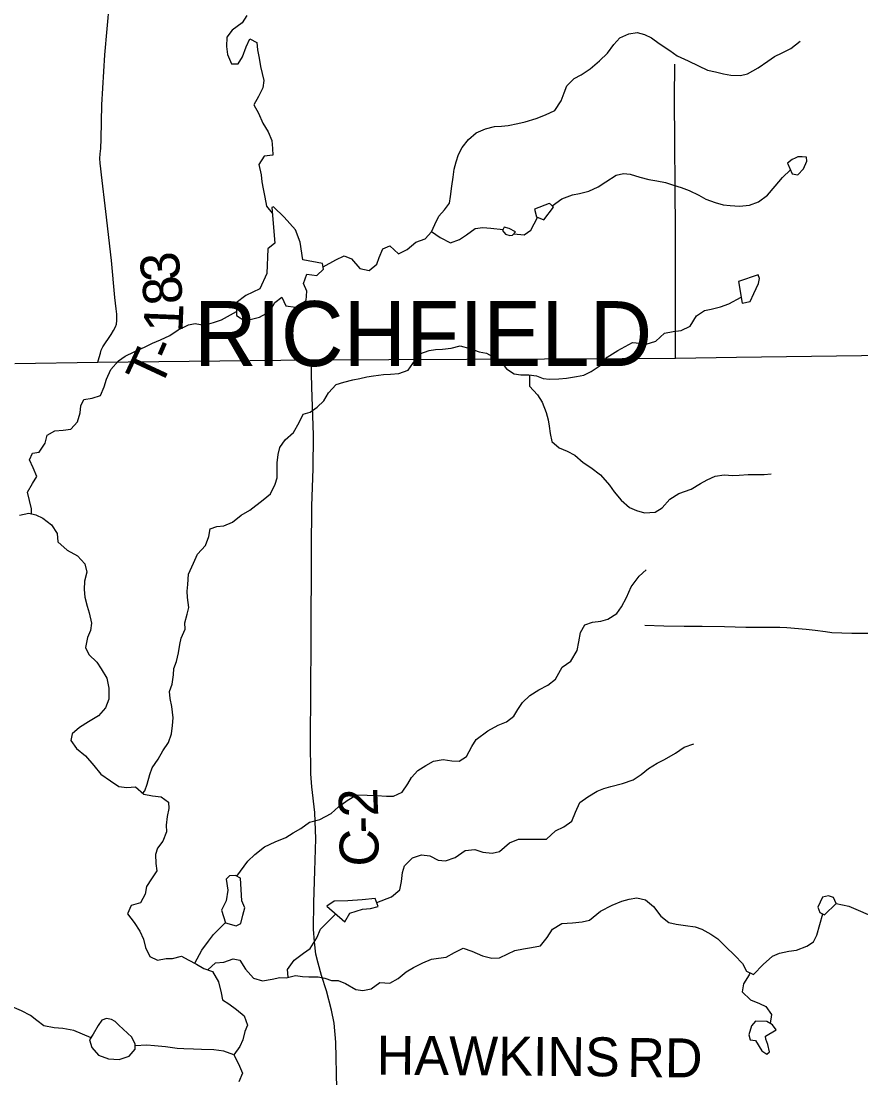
# Model space of a CAD drawing. Extents: x 0 to 34, y 0 to 22.
# Drawn here: x 3.306 to 4.531, y 17.388 to 18.93 of the extents above; entities that cross this region are included whole.
import ezdxf

# ---------------------------------------------------------------- set-up
doc = ezdxf.new("R2010")
doc.units = 0
for name, color, linetype in [('GM_X_City_Street', 7, 'Continuous'), ('GM_X_Corporation_Text', 7, 'Continuous'), ('GM_X_County_Road', 7, 'Continuous'), ('GM_X_County_Road_Text', 7, 'Continuous'), ('GM_X_Minor_Lake', 7, 'Continuous'), ('GM_X_Minor_River', 7, 'Continuous'), ('GM_X_State_Route', 7, 'Continuous'), ('GM_X_Township_Road', 7, 'Continuous'), ('GM_X_Township_Road_Text', 7, 'Continuous')]:
    doc.layers.add(name, color=color, linetype=linetype)

msp = doc.modelspace()

# ---------------------------------------------------------------- linework, layer by layer
at = {"layer": 'GM_X_City_Street'}
for points in [[(4.2606, 18.4383), (4.2606, 18.6235), (4.2594, 18.817), (4.2597, 18.8672)], [(4.2162, 18.0489), (4.2437, 18.0478), (4.2733, 18.0471), (4.2997, 18.0473), (4.3324, 18.0466), (4.3635, 18.0457), (4.4129, 18.0457), (4.4231, 18.0455), (4.4513, 18.0431), (4.4645, 18.0416), (4.4794, 18.0396), (4.4887, 18.0382), (4.5182, 18.0369), (4.5682, 18.0371)]]:
    msp.add_lwpolyline(points, dxfattribs=at)
at = {"layer": 'GM_X_County_Road'}
msp.add_lwpolyline([(3.7668, 17.3723), (3.7653, 17.4403), (3.7626, 17.4681), (3.7588, 17.4874), (3.7514, 17.5153), (3.7444, 17.5379), (3.7392, 17.5557), (3.7362, 17.5687), (3.7341, 17.5867), (3.7327, 17.6053), (3.7331, 17.644), (3.7347, 17.6903), (3.7359, 17.7372), (3.7343, 17.7754), (3.73, 17.8128), (3.7286, 17.8317), (3.7281, 17.8794), (3.729, 18.0253), (3.7295, 18.1581), (3.73, 18.2228), (3.7321, 18.2766), (3.7327, 18.326), (3.7301, 18.3961), (3.729, 18.4357)], dxfattribs=at)
at = {"layer": 'GM_X_Minor_Lake'}
for points in [[(4.4241, 18.7226), (4.4311, 18.7071), (4.439, 18.7057), (4.4473, 18.7145), (4.4521, 18.7255), (4.4517, 18.7316), (4.4453, 18.7319)], [(4.4453, 18.7319), (4.4393, 18.7318), (4.4354, 18.7302), (4.4309, 18.728), (4.4241, 18.7226)], [(3.676, 18.6061), (3.6659, 18.5977), (3.6647, 18.562), (3.6542, 18.5394), (3.6338, 18.5297), (3.6199, 18.519), (3.6204, 18.5007), (3.6323, 18.4925), (3.6538, 18.498), (3.669, 18.5061), (3.676, 18.5195), (3.6866, 18.5272), (3.692, 18.5147), (3.7065, 18.5129), (3.7219, 18.5226), (3.723, 18.5359), (3.7179, 18.5473), (3.7227, 18.5606), (3.7375, 18.5588), (3.7473, 18.5681), (3.7457, 18.5764), (3.7172, 18.5818), (3.7132, 18.6076), (3.7062, 18.6254), (3.6897, 18.6439), (3.6744, 18.6589)], [(3.6744, 18.6589), (3.6717, 18.6581), (3.676, 18.6061)], [(4.0551, 18.6557), (4.0578, 18.6443), (4.0685, 18.6399), (4.0827, 18.6586), (4.0785, 18.6631), (4.0762, 18.6639)], [(4.0762, 18.6639), (4.0551, 18.6557)], [(4.0273, 18.6227), (4.0181, 18.6272), (4.0109, 18.6294), (4.0083, 18.6245), (4.0129, 18.6192)], [(4.0129, 18.6192), (4.0189, 18.6171), (4.0228, 18.6177), (4.0273, 18.6227)], [(4.358, 18.5183), (4.3697, 18.5207), (4.3749, 18.5325), (4.382, 18.5474), (4.3835, 18.5547), (4.3811, 18.56), (4.3524, 18.5502)], [(4.3524, 18.5502), (4.358, 18.5183)], [(3.6263, 17.6797), (3.6187, 17.6838), (3.6099, 17.6829), (3.605, 17.6783), (3.6075, 17.662), (3.6053, 17.6468), (3.5982, 17.633), (3.6041, 17.6148), (3.6197, 17.6101), (3.6265, 17.6135), (3.6294, 17.6257), (3.6324, 17.6364), (3.6281, 17.6466)], [(3.6281, 17.6466), (3.6263, 17.6797)], [(4.4949, 17.643), (4.4914, 17.6513), (4.4838, 17.6539), (4.4754, 17.6519), (4.4684, 17.6374), (4.4711, 17.6298), (4.4783, 17.6261)], [(3.7783, 17.6161), (3.7857, 17.6287), (3.8043, 17.6346), (3.8157, 17.6355), (3.827, 17.6386), (3.8227, 17.65), (3.8034, 17.6479), (3.7829, 17.6466), (3.7628, 17.6464), (3.7519, 17.639)], [(3.7519, 17.639), (3.7783, 17.6161)], [(4.4783, 17.6261), (4.4949, 17.643)], [(3.424, 17.4726), (3.4184, 17.4649), (3.4113, 17.4523), (3.406, 17.4439), (3.4092, 17.4329), (3.4187, 17.4216), (3.4336, 17.416), (3.4492, 17.4154), (3.4639, 17.4201), (3.4726, 17.4305), (3.4725, 17.4377), (3.4675, 17.4479)], [(3.4675, 17.4479), (3.4485, 17.4651), (3.443, 17.4707), (3.4378, 17.4734), (3.4308, 17.4749), (3.424, 17.4726)], [(4.4077, 17.4586), (4.4023, 17.4658), (4.3939, 17.4707), (4.3776, 17.4713), (4.3716, 17.4644), (4.3676, 17.451), (4.3695, 17.4438), (4.3775, 17.4428), (4.3867, 17.4277), (4.394, 17.4228), (4.3981, 17.4263), (4.3954, 17.4372), (4.3927, 17.4448), (4.3922, 17.449)], [(4.3922, 17.449), (4.4077, 17.4586)]]:
    msp.add_lwpolyline(points, dxfattribs=at)
at = {"layer": 'GM_X_Minor_River'}
for points in [[(3.6351, 18.9379), (3.6287, 18.9275), (3.614, 18.9168), (3.6062, 18.9064), (3.6055, 18.8931), (3.6071, 18.881), (3.613, 18.8677), (3.6228, 18.8674), (3.6288, 18.8778), (3.6344, 18.8923), (3.6396, 18.9041), (3.6499, 18.8989), (3.6511, 18.8878), (3.6535, 18.8757), (3.6551, 18.8639), (3.6575, 18.8533), (3.6599, 18.8435), (3.6588, 18.8328), (3.6525, 18.8198), (3.6454, 18.8076), (3.6523, 18.7955), (3.6585, 18.7811), (3.6666, 18.7683), (3.6716, 18.7558), (3.6729, 18.744), (3.6734, 18.7342), (3.6605, 18.7329), (3.6526, 18.721), (3.6562, 18.7055), (3.6574, 18.6956), (3.659, 18.6854), (3.6614, 18.6729), (3.6642, 18.66), (3.6724, 18.6497)], [(3.7467, 18.5715), (3.7654, 18.5815), (3.7775, 18.5877), (3.7878, 18.5833), (3.8004, 18.5689), (3.8138, 18.566), (3.8251, 18.5752), (3.8284, 18.5852), (3.8336, 18.5977), (3.8442, 18.602), (3.8568, 18.5904), (3.8693, 18.5966), (3.8821, 18.6077), (3.8957, 18.6124), (3.9047, 18.6227), (3.9095, 18.6334), (3.9155, 18.6453), (3.9238, 18.6548), (3.9309, 18.6644), (3.9323, 18.6739), (3.9345, 18.6891), (3.9362, 18.7021), (3.9377, 18.7142), (3.9406, 18.7245), (3.9443, 18.7356), (3.9495, 18.7455), (3.9585, 18.757), (3.9698, 18.767), (3.9834, 18.7728), (3.9967, 18.776), (4.0069, 18.7768), (4.0168, 18.7777), (4.0308, 18.7805), (4.0414, 18.7829), (4.0573, 18.7879), (4.0709, 18.793), (4.0849, 18.7996), (4.0939, 18.8137), (4.0983, 18.8252), (4.102, 18.8355), (4.1129, 18.8462), (4.1231, 18.8516), (4.1363, 18.8605), (4.1499, 18.872), (4.1616, 18.8832), (4.1709, 18.8958), (4.1796, 18.9057), (4.1928, 18.9112), (4.2049, 18.9132), (4.2156, 18.9103), (4.2259, 18.9054), (4.2369, 18.8975), (4.2526, 18.8871), (4.2633, 18.8792), (4.2793, 18.8721), (4.2942, 18.8646), (4.3075, 18.8583), (4.3193, 18.8561), (4.3307, 18.8532), (4.3413, 18.851), (4.3554, 18.8508), (4.3656, 18.8532), (4.3815, 18.862), (4.3954, 18.8717), (4.4052, 18.8782), (4.4162, 18.8837), (4.429, 18.8902), (4.4426, 18.9006)], [(4.0809, 18.6606), (4.0948, 18.6709), (4.1103, 18.6767), (4.1205, 18.6787), (4.1345, 18.6819), (4.1481, 18.6881), (4.1591, 18.6954), (4.1742, 18.7054), (4.1851, 18.7078), (4.1946, 18.7068), (4.2087, 18.7023), (4.222, 18.6991), (4.2334, 18.6969), (4.246, 18.6943), (4.2578, 18.6907), (4.2692, 18.687), (4.2806, 18.6829), (4.2947, 18.6762), (4.305, 18.6702), (4.3187, 18.6654), (4.3305, 18.6621), (4.3404, 18.661), (4.3541, 18.66), (4.3685, 18.6613), (4.3817, 18.6664), (4.3949, 18.676), (4.4062, 18.6894), (4.4167, 18.7016), (4.4283, 18.7131)], [(4.0247, 18.6198), (4.0398, 18.6183), (4.0496, 18.6252), (4.0596, 18.6436)], [(3.9048, 18.6229), (3.9173, 18.6141), (3.9326, 18.6063), (3.9458, 18.6113), (3.9556, 18.6183), (3.9684, 18.6275), (3.9798, 18.6291), (3.9912, 18.6281), (4.0091, 18.626)], [(4.282, 18.4849), (4.2914, 18.4998), (4.3031, 18.5079), (4.3129, 18.5099), (4.3262, 18.5131), (4.3386, 18.5174), (4.3564, 18.5274)], [(3.321, 18.2113), (3.3213, 18.2186), (3.3181, 18.2307), (3.3154, 18.2429), (3.3225, 18.2555), (3.3288, 18.2658), (3.3238, 18.2783), (3.3184, 18.29), (3.3224, 18.2999), (3.3323, 18.3012), (3.3413, 18.3142), (3.3442, 18.326), (3.3552, 18.3322), (3.3673, 18.333), (3.3787, 18.3347), (3.3884, 18.3454), (3.3921, 18.3584), (3.3932, 18.3686), (3.3976, 18.3782), (3.4098, 18.3798), (3.4219, 18.3837), (3.4271, 18.3963), (3.4304, 18.4077), (3.4371, 18.4219), (3.448, 18.4345), (3.4578, 18.4411), (3.471, 18.4473), (3.4869, 18.4546), (3.4978, 18.4601), (3.5092, 18.4651), (3.5232, 18.4713), (3.5352, 18.4794), (3.55, 18.4868), (3.5598, 18.4888), (3.5731, 18.4862), (3.5867, 18.4905), (3.5985, 18.4944), (3.6203, 18.5062)], [(3.4835, 17.8037), (3.4866, 17.8071), (3.49, 17.8167), (3.4936, 17.8308), (3.4973, 17.8407), (3.5059, 17.8533), (3.5127, 17.8655), (3.5209, 17.8778), (3.5253, 17.8903), (3.5268, 17.9025), (3.5278, 17.9135), (3.5261, 17.9299), (3.5237, 17.942), (3.5225, 17.9519), (3.5266, 17.9626), (3.5284, 17.9763), (3.5287, 17.9858), (3.5327, 17.9957), (3.5357, 18.0086), (3.5375, 18.0204), (3.5393, 18.0299), (3.5452, 18.0429), (3.5451, 18.0524), (3.5481, 18.0646), (3.5506, 18.0745), (3.5486, 18.0889), (3.5485, 18.0984), (3.5492, 18.1079), (3.5502, 18.1231), (3.5573, 18.1392), (3.5632, 18.1525), (3.5752, 18.1648), (3.5801, 18.1781), (3.5819, 18.1895), (3.5917, 18.1927), (3.6019, 18.1939), (3.6144, 18.199), (3.6272, 18.2094), (3.6397, 18.2163), (3.6593, 18.2317), (3.6698, 18.2405), (3.6769, 18.2543), (3.6795, 18.2638), (3.6798, 18.2748), (3.6797, 18.2855), (3.6811, 18.2976), (3.6836, 18.3079), (3.6911, 18.319), (3.7032, 18.3298), (3.7118, 18.3443), (3.7177, 18.3565), (3.7276, 18.3596), (3.7378, 18.3666), (3.7475, 18.3762), (3.7546, 18.3876), (3.7659, 18.3999), (3.7769, 18.4034), (3.7898, 18.4066), (3.8, 18.4086), (3.8102, 18.411), (3.8201, 18.4126), (3.8345, 18.4146), (3.8451, 18.4151), (3.8572, 18.416), (3.8705, 18.421), (3.8776, 18.4306), (3.8877, 18.4444), (3.9013, 18.4494), (3.9108, 18.4507), (3.9207, 18.4515), (3.9336, 18.4528), (3.9468, 18.4563), (3.9609, 18.4523), (3.9742, 18.4475), (3.9848, 18.4457), (3.9963, 18.4393), (4.0062, 18.4329), (4.0143, 18.4228), (4.0253, 18.4153), (4.0352, 18.4138), (4.0466, 18.4139), (4.058, 18.4125), (4.0675, 18.4088), (4.077, 18.4078), (4.0903, 18.4079), (4.1017, 18.4091), (4.1161, 18.4116), (4.1271, 18.4136), (4.1376, 18.4186), (4.1508, 18.4275), (4.161, 18.4397), (4.1765, 18.4494), (4.1874, 18.4555), (4.198, 18.461), (4.2086, 18.4603), (4.2181, 18.4589), (4.2321, 18.4632), (4.2445, 18.4747), (4.2574, 18.4771), (4.2688, 18.4787), (4.282, 18.4849)], [(4.0479, 18.4138), (4.0479, 18.3976), (4.0594, 18.3848), (4.0663, 18.3742), (4.0721, 18.3591), (4.0749, 18.3485), (4.0765, 18.339), (4.0777, 18.3284), (4.0805, 18.3166), (4.0908, 18.3076), (4.1026, 18.3028), (4.1141, 18.2968), (4.1259, 18.2859), (4.137, 18.2788), (4.1515, 18.2679), (4.1646, 18.2532), (4.1711, 18.2434), (4.1814, 18.2313), (4.1937, 18.2204), (4.204, 18.2159), (4.2154, 18.2126), (4.2313, 18.2135), (4.2415, 18.2201), (4.2524, 18.2327), (4.2656, 18.2408), (4.2838, 18.2471), (4.297, 18.2552), (4.3068, 18.2606), (4.3185, 18.266), (4.3318, 18.268), (4.3443, 18.267), (4.3538, 18.2675), (4.3667, 18.2684), (4.3902, 18.2686), (4.4001, 18.2694)], [(3.3035, 18.2093), (3.3172, 18.2121), (3.3274, 18.2099), (3.3377, 18.2047), (3.3503, 18.1953), (3.3584, 18.1825), (3.3597, 18.1703), (3.373, 18.1583), (3.3883, 18.1497), (3.399, 18.1384), (3.4018, 18.1263), (3.3985, 18.113), (3.3978, 18.1008), (3.3991, 18.0898), (3.4026, 18.0765), (3.4054, 18.0667), (3.4085, 18.0519), (3.4071, 18.0412), (3.403, 18.0309), (3.4001, 18.0161), (3.4048, 18.0059), (3.4166, 17.995), (3.4228, 17.9851), (3.4309, 17.9715), (3.4341, 17.9567), (3.4338, 17.9408), (3.429, 17.9282), (3.4189, 17.9163), (3.4041, 17.9078), (3.3913, 17.8993), (3.3804, 17.8901), (3.3786, 17.8806), (3.3866, 17.8689), (3.4, 17.858), (3.4123, 17.8441), (3.4223, 17.8316), (3.4364, 17.8219), (3.4486, 17.8132), (3.4604, 17.8118), (3.4729, 17.8131), (3.4851, 17.8022), (3.4977, 17.8), (3.5102, 17.7986), (3.5209, 17.7908), (3.5214, 17.7813), (3.5192, 17.7695), (3.5178, 17.7569), (3.5179, 17.7474), (3.5127, 17.7337), (3.5052, 17.7237), (3.5023, 17.7142), (3.5028, 17.7009), (3.504, 17.6903), (3.4961, 17.6788), (3.489, 17.6677), (3.4868, 17.6563), (3.4801, 17.6437), (3.4665, 17.6398), (3.4613, 17.6279), (3.4709, 17.6151), (3.4794, 17.6023), (3.4844, 17.5905), (3.4875, 17.5784), (3.4937, 17.5655), (3.5048, 17.56), (3.5177, 17.5627), (3.5271, 17.5624), (3.54, 17.566), (3.5496, 17.5608), (3.5618, 17.5544), (3.5724, 17.5481), (3.585, 17.5436), (3.5939, 17.5285), (3.5978, 17.5126), (3.5998, 17.5023), (3.6093, 17.4963), (3.6204, 17.4881), (3.6315, 17.4791), (3.6362, 17.4654), (3.6325, 17.4559), (3.6295, 17.4437), (3.6251, 17.4342), (3.6165, 17.4219), (3.623, 17.4087), (3.6288, 17.3951), (3.6236, 17.3825)], [(3.6207, 17.6827), (3.6367, 17.7044), (3.6472, 17.714), (3.6612, 17.7256), (3.6767, 17.7329), (3.6922, 17.7388), (3.7031, 17.7457), (3.714, 17.7523), (3.7269, 17.7612), (3.7416, 17.7655), (3.7582, 17.774), (3.7692, 17.7836), (3.7816, 17.7932), (3.7952, 17.8013), (3.8111, 17.8007), (3.8252, 17.8001), (3.8392, 17.7995), (3.8495, 17.7992), (3.8619, 17.8054), (3.8702, 17.8172), (3.8754, 17.8268), (3.8848, 17.8367), (3.8965, 17.8441), (3.9078, 17.8503), (3.9219, 17.8527), (3.9344, 17.8509), (3.945, 17.8506), (3.9556, 17.8572), (3.9634, 17.8717), (3.9698, 17.882), (3.9868, 17.8947), (4.0022, 17.9028), (4.0143, 17.9079), (4.0249, 17.916), (4.0309, 17.9259), (4.0376, 17.9358), (4.0481, 17.9462), (4.0614, 17.9543), (4.0746, 17.9613), (4.0855, 17.9701), (4.0956, 17.9873), (4.108, 17.9965), (4.1174, 18.0118), (4.1199, 18.0244), (4.1221, 18.0381), (4.1284, 18.0495), (4.1394, 18.0531), (4.1519, 18.0547), (4.1618, 18.0575), (4.175, 18.0659), (4.1821, 18.0755), (4.1892, 18.0889), (4.1962, 18.1045), (4.2079, 18.1202), (4.2177, 18.1294)], [(3.8249, 17.6442), (3.8466, 17.6525), (3.8587, 17.6628), (3.8612, 17.675), (3.8626, 17.688), (3.8652, 17.6975), (3.8768, 17.7094), (3.8901, 17.7137), (3.9022, 17.7123), (3.9144, 17.7059), (3.9251, 17.7049), (3.9395, 17.71), (3.9538, 17.72), (3.9678, 17.7213), (3.9796, 17.7176), (3.9933, 17.7162), (4.0039, 17.7186), (4.0186, 17.7312), (4.0318, 17.7367), (4.0451, 17.7364), (4.0724, 17.7367), (4.0856, 17.749), (4.0977, 17.7548), (4.1094, 17.7629), (4.1146, 17.7758), (4.1213, 17.79), (4.133, 17.7984), (4.1465, 17.8065), (4.1564, 17.8104), (4.1662, 17.8132), (4.1836, 17.8179), (4.1988, 17.8234), (4.2108, 17.8307), (4.2214, 17.8395), (4.2338, 17.8476), (4.2448, 17.853), (4.2607, 17.8623), (4.2735, 17.8708), (4.2875, 17.8759)], [(3.5783, 17.546), (3.5894, 17.5562), (3.6016, 17.5574), (3.6156, 17.5621), (3.6251, 17.56), (3.6332, 17.5471), (3.645, 17.5339), (3.6584, 17.5299), (3.6724, 17.5323), (3.6834, 17.5347), (3.6929, 17.5344), (3.7061, 17.5375), (3.7164, 17.5365), (3.7259, 17.5358), (3.7395, 17.5356), (3.749, 17.5338), (3.7589, 17.5304), (3.7688, 17.5305), (3.7791, 17.5261), (3.7943, 17.5171), (3.8046, 17.5157), (3.8167, 17.5184), (3.8295, 17.5277), (3.844, 17.5267), (3.856, 17.5333), (3.8677, 17.5429), (3.8787, 17.5494), (3.8919, 17.556), (3.9047, 17.5614), (3.915, 17.5631), (3.926, 17.5647), (3.9384, 17.5713), (3.9509, 17.5775), (3.9638, 17.573), (3.9791, 17.5663), (3.9928, 17.563), (4.0041, 17.5635), (4.0162, 17.5693), (4.0264, 17.574), (4.0389, 17.5768), (4.0507, 17.5784), (4.0636, 17.5812), (4.0733, 17.5931), (4.0812, 17.6053), (4.0948, 17.6134), (4.1103, 17.6147), (4.1244, 17.616), (4.1353, 17.6183), (4.1515, 17.6318), (4.1685, 17.6403), (4.1825, 17.6461), (4.1931, 17.6493), (4.2041, 17.6509), (4.217, 17.648), (4.2285, 17.6382), (4.2393, 17.6243), (4.2511, 17.6149), (4.2618, 17.6127), (4.2754, 17.6109), (4.2895, 17.6088), (4.299, 17.6054), (4.3124, 17.598), (4.3223, 17.5912), (4.3338, 17.5799), (4.3472, 17.5671), (4.3583, 17.5551), (4.3641, 17.5441), (4.3747, 17.5393), (4.3886, 17.5538), (4.4022, 17.5657), (4.4124, 17.5704), (4.426, 17.5732), (4.4374, 17.5748), (4.4522, 17.5807), (4.462, 17.5868), (4.4668, 17.5964), (4.4756, 17.6275)], [(4.4949, 17.643), (4.5135, 17.639), (4.5272, 17.633), (4.5417, 17.6267), (4.5539, 17.623), (4.5641, 17.6243), (4.5758, 17.6297), (4.5894, 17.6397), (4.6099, 17.6616)], [(3.6957, 17.5351), (3.6946, 17.5465), (3.7044, 17.5603), (3.718, 17.5703), (3.7278, 17.5769), (3.7375, 17.5929), (3.7427, 17.6055), (3.765, 17.6276)], [(3.5593, 17.5557), (3.5699, 17.5746), (3.5793, 17.588), (3.5868, 17.5976), (3.604, 17.6151)], [(4.369, 17.5419), (4.3683, 17.5388), (4.3597, 17.5258), (4.3579, 17.5137), (4.3701, 17.502), (4.3831, 17.4968), (4.3926, 17.4923), (4.4007, 17.4806), (4.3987, 17.4679)], [(3.408, 17.447), (3.3831, 17.4577), (3.3668, 17.4602), (3.3543, 17.4616), (3.3394, 17.4645), (3.3291, 17.472), (3.3196, 17.4792), (3.3066, 17.4863), (3.2884, 17.4941)], [(3.6165, 17.4219), (3.602, 17.4275), (3.5872, 17.4293), (3.5693, 17.4299), (3.5576, 17.4305), (3.5435, 17.4307), (3.5336, 17.4314), (3.5169, 17.4335), (3.5006, 17.4353), (3.4892, 17.4363), (3.4725, 17.4353)]]:
    msp.add_lwpolyline(points, dxfattribs=at)
at = {"layer": 'GM_X_State_Route'}
msp.add_line((4.1827, 18.4379), (4.2007, 18.438), dxfattribs=at)
for points in [[(4.3499, 18.4395), (4.5684, 18.4425), (4.8237, 18.4481), (4.8894, 18.4497), (4.994, 18.4507), (5.109, 18.453), (5.3585, 18.4586), (5.7621, 18.4652)], [(3.2967, 18.4306), (3.4179, 18.4325), (3.729, 18.4357), (4.1827, 18.4379)], [(4.2007, 18.438), (4.2606, 18.4383), (4.3499, 18.4395)]]:
    msp.add_lwpolyline(points, dxfattribs=at)
at = {"layer": 'GM_X_Township_Road'}
msp.add_lwpolyline([(3.4179, 18.4325), (3.4199, 18.4391), (3.4218, 18.4456), (3.4227, 18.45), (3.4251, 18.455), (3.4375, 18.473), (3.441, 18.4785), (3.4437, 18.4838), (3.445, 18.4881), (3.4455, 18.4932), (3.4458, 18.4974), (3.4458, 18.5025), (3.4447, 18.51), (3.4429, 18.5267), (3.4378, 18.5808), (3.4297, 18.6522), (3.4234, 18.7058), (3.4221, 18.7144), (3.4213, 18.7227), (3.4211, 18.7295), (3.4213, 18.7364), (3.4221, 18.7442), (3.4227, 18.7583), (3.424, 18.8076), (3.4284, 18.8808), (3.435, 18.9564)], dxfattribs=at)

# ---------------------------------------------------------------- texts
at = {"layer": 'GM_X_Corporation_Text'}
msp.add_text('RICHFIELD', height=0.0947, rotation=0, dxfattribs=at).set_placement((3.5583, 18.4268))
at = {"layer": 'GM_X_County_Road_Text'}
for s, rotation, p in [('2', 92.5338, (3.8272, 17.7701)), ('-', 91.5121, (3.8279, 17.7457)), ('C', 88.8251, (3.8269, 17.6961))]:
    msp.add_text(s, height=0.0568, rotation=rotation, dxfattribs=at).set_placement(p)
at = {"layer": 'GM_X_Township_Road_Text'}
for s, height, rotation, p in [('3', 0.0568, 95.4988, (3.539, 18.5536)), ('8', 0.0568, 95.7425, (3.5425, 18.5188)), ('1', 0.0568, 87.731, (3.5414, 18.4752)), ('T', 0.0568, 65.0527, (3.5085, 18.3916)), ('-', 0.0568, 66.6926, (3.5271, 18.4317)), ('HAWKINS', 0.05682, 359.5648, (3.8246, 17.3932)), ('RD', 0.05682, 359.5045, (4.1902, 17.3898))]:
    msp.add_text(s, height=height, rotation=rotation, dxfattribs=at).set_placement(p)

doc.saveas('drawing.dxf')
